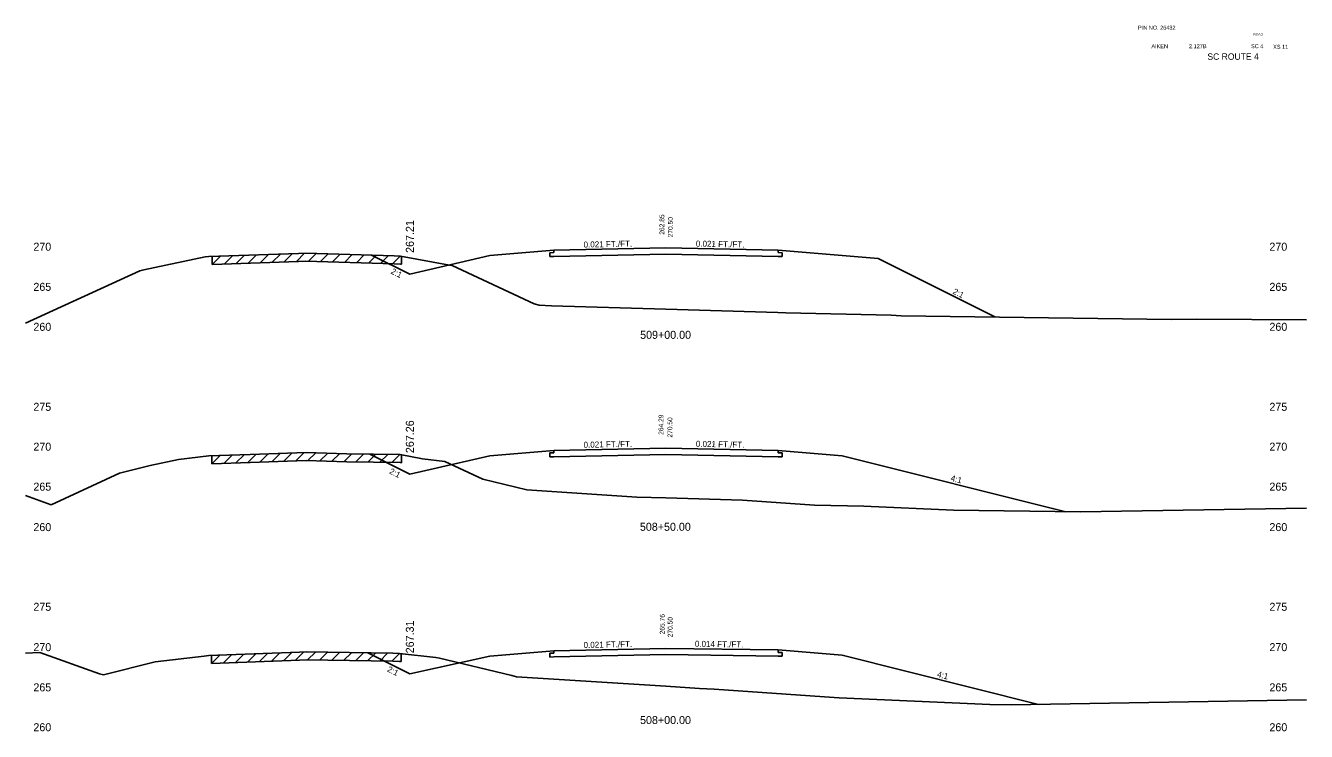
# Model space of a CAD drawing. Extents: x 883 to 1160, y 1002 to 4323.
# Drawn here: x 1000 to 1160, y 2165.1 to 2253.3 of the extents above; entities that cross this region are included whole.
import ezdxf

# ---------------------------------------------------------------- set-up
doc = ezdxf.new("R2010")
doc.units = 0
for name, color, linetype in [('Level 1', 7, 'Continuous'), ('Level 10', 7, 'Continuous'), ('Level 11', 7, 'Continuous'), ('Level 12', 7, 'Continuous'), ('Level 3', 7, 'Continuous'), ('Level 32', 7, 'Continuous'), ('Level 33', 7, 'Continuous'), ('Level 59', 7, 'Continuous'), ('Level 6', 7, 'Continuous'), ('Level 60', 7, 'Continuous'), ('Level 61', 7, 'Continuous'), ('Level 7', 7, 'Continuous')]:
    doc.layers.add(name, color=color, linetype=linetype)

msp = doc.modelspace()

# ---------------------------------------------------------------- linework, layer by layer
at = {"layer": 'Level 11'}
for p, q in [((1066, 2224.91), (1065.5, 2224.9)), ((1065.5, 2224.9), (1065.5, 2224.42)), ((1065.5, 2224.42), (1066, 2224.43)), ((1066, 2225.21), (1066, 2224.91)), ((1094, 2224.91), (1094, 2225.21)), ((1094.5, 2224.9), (1094, 2224.91)), ((1094, 2224.43), (1094.5, 2224.42)), ((1094.5, 2224.42), (1094.5, 2224.9)), ((1066, 2200.21), (1066, 2199.91)), ((1094, 2199.91), (1094, 2200.21)), ((1066, 2199.91), (1065.5, 2199.9)), ((1065.5, 2199.9), (1065.5, 2199.42)), ((1065.5, 2199.42), (1066, 2199.43)), ((1094.5, 2199.9), (1094, 2199.91)), ((1094, 2199.43), (1094.5, 2199.42)), ((1094.5, 2199.42), (1094.5, 2199.9)), ((1066, 2174.91), (1065.5, 2174.9)), ((1065.5, 2174.9), (1065.5, 2174.42)), ((1065.5, 2174.42), (1066, 2174.43)), ((1066, 2175.21), (1066, 2174.91)), ((1094, 2175), (1094, 2175.3)), ((1094.5, 2174.99), (1094, 2175)), ((1094, 2174.52), (1094.5, 2174.51)), ((1094.5, 2174.51), (1094.5, 2174.99))]:
    msp.add_line(p, q, dxfattribs=at)
at = {"layer": 'Level 12'}
for p, q in [((1080, 2224.72), (1066, 2224.43)), ((1094, 2224.43), (1080, 2224.72)), ((1080, 2199.72), (1066, 2199.43)), ((1094, 2199.43), (1080, 2199.72)), ((1080, 2174.72), (1066, 2174.43)), ((1094, 2174.52), (1080, 2174.72))]:
    msp.add_line(p, q, dxfattribs=at)
at = {"layer": 'Level 59'}
for p, q in [((1066, 2225.21), (1080, 2225.5)), ((1080, 2225.5), (1094, 2225.21)), ((1066, 2200.21), (1080, 2200.5)), ((1080, 2200.5), (1094, 2200.21)), ((1066, 2175.21), (1080, 2175.5)), ((1080, 2175.5), (1094, 2175.3))]:
    msp.add_line(p, q, dxfattribs=at)
at = {"layer": 'Level 6'}
for p, q in [((1058, 2224.54), (1066, 2225.21)), ((1094, 2225.21), (1106.5, 2224.17)), ((1058, 2199.54), (1066, 2200.21)), ((1094, 2200.21), (1102, 2199.54)), ((1058, 2174.54), (1066, 2175.21)), ((1094, 2175.3), (1102, 2174.63))]:
    msp.add_line(p, q, dxfattribs=at)
at = {"layer": 'Level 60'}
for p, q in [((1014.76, 2222.77), (1022.41, 2224.37)), ((1022.41, 2224.37), (1022.9, 2224.42)), ((1022.9, 2224.42), (1034.11, 2224.82)), ((1034.11, 2224.82), (1035, 2224.86)), ((1035, 2224.86), (1046.04, 2224.5)), ((1046.04, 2224.5), (1046.85, 2224.49)), ((1046.85, 2224.49), (1052.97, 2223.36)), ((1000, 2216.09), (1014.26, 2222.65)), ((1014.26, 2222.65), (1014.76, 2222.77)), ((1052.97, 2223.36), (1053.3, 2223.32)), ((1053.3, 2223.32), (1063.53, 2218.5)), ((1063.53, 2218.5), (1064.15, 2218.35)), ((1064.15, 2218.35), (1065.69, 2218.25)), ((1065.69, 2218.25), (1080, 2217.85)), ((1080, 2217.85), (1093.99, 2217.45)), ((1093.99, 2217.45), (1094.99, 2217.38)), ((1094.99, 2217.38), (1108.12, 2217.1)), ((1108.12, 2217.1), (1109.36, 2217.04)), ((1109.36, 2217.04), (1143.14, 2216.57)), ((1143.14, 2216.57), (1146.33, 2216.62)), ((1146.33, 2216.62), (1160, 2216.51)), ((1015.57, 2198.34), (1019.1, 2199.07)), ((1019.1, 2199.07), (1022.88, 2199.52)), ((1022.88, 2199.52), (1028.06, 2199.71)), ((1028.06, 2199.71), (1035.03, 2199.97)), ((1035.03, 2199.97), (1040.12, 2199.8)), ((1040.12, 2199.8), (1046.77, 2199.69)), ((1046.77, 2199.69), (1049.6, 2199.17)), ((1049.6, 2199.17), (1052.38, 2198.85)), ((1052.38, 2198.85), (1057.11, 2196.62)), ((1003.18, 2193.44), (1011.73, 2197.37)), ((1011.73, 2197.37), (1015.57, 2198.34)), ((1057.11, 2196.62), (1062.62, 2195.29)), ((1062.62, 2195.29), (1076.37, 2194.39)), ((1000, 2194.57), (1003.18, 2193.44)), ((1076.37, 2194.39), (1080, 2194.29)), ((1080, 2194.29), (1089.57, 2194.02)), ((1089.57, 2194.02), (1098.56, 2193.4)), ((1098.56, 2193.4), (1104.71, 2193.26)), ((1104.71, 2193.26), (1115.91, 2192.76)), ((1115.91, 2192.76), (1131.77, 2192.54)), ((1131.77, 2192.54), (1160, 2193.01)), ((1000, 2174.92), (1001.79, 2175)), ((1001.79, 2175), (1009.23, 2172.3)), ((1016.18, 2173.8), (1022.31, 2174.54)), ((1022.31, 2174.54), (1022.89, 2174.62)), ((1022.89, 2174.62), (1034.21, 2175.03)), ((1034.21, 2175.03), (1035.05, 2175.05)), ((1035.05, 2175.05), (1045.88, 2174.88)), ((1045.88, 2174.88), (1046.72, 2174.87)), ((1046.72, 2174.87), (1051.26, 2174.35)), ((1009.71, 2172.19), (1016.18, 2173.8)), ((1051.26, 2174.35), (1051.7, 2174.29)), ((1051.7, 2174.29), (1060.76, 2172.1)), ((1009.23, 2172.3), (1009.71, 2172.19)), ((1060.76, 2172.1), (1061.32, 2171.96)), ((1061.32, 2171.96), (1080, 2170.76)), ((1080, 2170.76), (1084.18, 2170.49)), ((1084.18, 2170.49), (1086.01, 2170.4)), ((1086.01, 2170.4), (1101.01, 2169.36)), ((1101.01, 2169.36), (1101.62, 2169.33)), ((1101.62, 2169.33), (1120.46, 2168.48)), ((1120.46, 2168.48), (1123.1, 2168.44)), ((1123.1, 2168.44), (1160, 2169.08))]:
    msp.add_line(p, q, dxfattribs=at)
at = {"layer": 'Level 61'}
for p, q in [((1024.35, 2224.48), (1023.32, 2223.44)), ((1023.32, 2224.44), (1023.32, 2223.44)), ((1025.85, 2224.53), (1024.82, 2223.49)), ((1027.35, 2224.58), (1026.32, 2223.55)), ((1028.85, 2224.64), (1027.82, 2223.6)), ((1030.35, 2224.69), (1029.32, 2223.65)), ((1031.85, 2224.74), (1030.82, 2223.71)), ((1033.35, 2224.8), (1032.32, 2223.76)), ((1034.85, 2224.85), (1033.82, 2223.81)), ((1036.28, 2224.82), (1035.32, 2223.85)), ((1037.78, 2224.77), (1036.82, 2223.8)), ((1039.28, 2224.72), (1038.32, 2223.75)), ((1040.78, 2224.67), (1039.82, 2223.7)), ((1042.28, 2224.62), (1041.32, 2223.65)), ((1043.78, 2224.57), (1042.82, 2223.61)), ((1045.28, 2224.53), (1044.32, 2223.56)), ((1046.8, 2224.49), (1045.82, 2223.51)), ((1046.97, 2223.47), (1046.97, 2224.47)), ((1023.32, 2223.44), (1034.11, 2223.82)), ((1034.11, 2223.82), (1035, 2223.86)), ((1035, 2223.86), (1046.04, 2223.5)), ((1046.04, 2223.5), (1046.85, 2223.49)), ((1046.85, 2223.49), (1046.97, 2223.47)), ((1024.31, 2199.58), (1023.27, 2198.54)), ((1023.27, 2199.54), (1023.27, 2198.54)), ((1023.27, 2198.54), (1028.06, 2198.71)), ((1025.81, 2199.63), (1024.77, 2198.59)), ((1027.31, 2199.68), (1026.27, 2198.65)), ((1028.81, 2199.74), (1027.77, 2198.7)), ((1028.06, 2198.71), (1035.03, 2198.97)), ((1030.31, 2199.79), (1029.27, 2198.75)), ((1031.81, 2199.85), (1030.77, 2198.81)), ((1033.31, 2199.9), (1032.27, 2198.86)), ((1034.81, 2199.96), (1033.77, 2198.92)), ((1035.03, 2198.97), (1040.12, 2198.8)), ((1036.24, 2199.93), (1035.27, 2198.96)), ((1037.74, 2199.88), (1036.77, 2198.91)), ((1039.24, 2199.83), (1038.27, 2198.86)), ((1040.75, 2199.79), (1039.77, 2198.81)), ((1040.12, 2198.8), (1046.77, 2198.69)), ((1042.26, 2199.77), (1041.27, 2198.78)), ((1043.76, 2199.74), (1042.77, 2198.76)), ((1045.26, 2199.72), (1044.27, 2198.73)), ((1046.76, 2199.69), (1045.77, 2198.71)), ((1046.77, 2198.69), (1046.95, 2198.66)), ((1046.95, 2198.66), (1046.95, 2199.66)), ((1024.27, 2174.67), (1023.23, 2173.63)), ((1023.23, 2174.63), (1023.23, 2173.63)), ((1025.77, 2174.72), (1024.73, 2173.68)), ((1027.27, 2174.78), (1026.23, 2173.74)), ((1028.77, 2174.83), (1027.73, 2173.79)), ((1030.27, 2174.89), (1029.23, 2173.85)), ((1031.77, 2174.94), (1030.73, 2173.9)), ((1033.27, 2175), (1032.23, 2173.96)), ((1034.76, 2175.05), (1033.73, 2174.02)), ((1036.22, 2175.03), (1035.23, 2174.05)), ((1037.72, 2175.01), (1036.73, 2174.02)), ((1039.22, 2174.98), (1038.23, 2174)), ((1040.72, 2174.96), (1039.73, 2173.98)), ((1042.22, 2174.94), (1041.23, 2173.95)), ((1043.72, 2174.91), (1042.73, 2173.93)), ((1045.22, 2174.89), (1044.23, 2173.9)), ((1046.72, 2174.87), (1045.73, 2173.88)), ((1046.93, 2173.85), (1046.93, 2174.85)), ((1023.23, 2173.63), (1034.21, 2174.03)), ((1034.21, 2174.03), (1035.05, 2174.05)), ((1035.05, 2174.05), (1045.88, 2173.88)), ((1045.88, 2173.88), (1046.72, 2173.87)), ((1046.72, 2173.87), (1046.93, 2173.85))]:
    msp.add_line(p, q, dxfattribs=at)
at = {"layer": 'Level 7'}
for p, q in [((1043.23, 2224.59), (1048, 2222.21)), ((1048, 2222.21), (1058, 2224.54)), ((1106.5, 2224.17), (1121.08, 2216.88)), ((1043, 2199.76), (1048, 2197.26)), ((1048, 2197.26), (1058, 2199.54)), ((1102, 2199.54), (1129.93, 2192.56)), ((1042.76, 2174.93), (1048, 2172.31)), ((1048, 2172.31), (1058, 2174.54)), ((1102, 2174.63), (1126.53, 2168.5))]:
    msp.add_line(p, q, dxfattribs=at)

# ---------------------------------------------------------------- texts
at = {"layer": 'Level 1'}
for s, height, p in [('PIN NO. 26432', 0.5, (1138.97, 2252.75)), ('AIKEN', 0.5, (1140.64, 2250.44)), (' 2.127B', 0.5, (1145.15, 2250.44)), ('SC ROUTE 4', 0.8, (1147.63, 2248.99)), ('SC 4', 0.5, (1153.09, 2250.44)), ('XS 11', 0.5, (1155.85, 2250.36)), ('509+00.00', 1, (1076.77, 2214.15)), ('508+50.00', 1, (1076.74, 2190.18)), ('508+00.00', 1, (1076.76, 2166.05))]:
    msp.add_text(s, height=height, dxfattribs=at).set_placement(p)
at = {"layer": 'Level 10'}
for s, p in [('262.85', (1079.79, 2227.15)), ('264.29', (1079.67, 2202.16)), ('265.76', (1079.83, 2177.25))]:
    msp.add_text(s, height=0.6, rotation=90, dxfattribs=at).set_placement(p)
at = {"layer": 'Level 3'}
for s, height, p in [('ROAD', 0.3, (1153.38, 2252.02)), (' 270', 1, (1000.6, 2225.15)), (' 270', 1, (1155.01, 2225.15)), (' 265', 1, (1000.6, 2220.14)), (' 265', 1, (1155.01, 2220.14)), (' 260', 1, (1000.6, 2215.15)), (' 260', 1, (1155.01, 2215.15)), (' 275', 1, (1000.6, 2205.16)), (' 275', 1, (1155.01, 2205.16)), (' 270', 1, (1000.6, 2200.18)), (' 270', 1, (1155.01, 2200.18)), (' 265', 1, (1000.6, 2195.19)), (' 265', 1, (1155.01, 2195.19)), (' 260', 1, (1000.6, 2190.14)), (' 260', 1, (1155.01, 2190.14)), (' 275', 1, (1000.6, 2180.19)), (' 275', 1, (1155.01, 2180.19)), (' 270', 1, (1000.6, 2175.15)), (' 270', 1, (1155.01, 2175.15)), (' 265', 1, (1000.6, 2170.13)), (' 265', 1, (1155.01, 2170.13)), (' 260', 1, (1000.6, 2165.15)), (' 260', 1, (1155.01, 2165.15))]:
    msp.add_text(s, height=height, dxfattribs=at).set_placement(p)
at = {"layer": 'Level 32'}
for s, rotation, p in [('0.021 FT./FT.', 1.1916, (1069.71, 2225.54)), ('0.021 FT./FT.', 358.8084, (1083.72, 2225.67)), ('2:1', 333.435, (1045.55, 2222.34)), ('2:1', 333.435, (1115.75, 2219.82)), ('0.021 FT./FT.', 1.1916, (1069.71, 2200.54)), ('0.021 FT./FT.', 358.8084, (1083.72, 2200.67)), ('2:1', 333.435, (1045.36, 2197.37)), ('4:1', 345.9638, (1115.51, 2196.42)), ('0.021 FT./FT.', 1.1916, (1069.71, 2175.54)), ('0.014 FT./FT.', 359.1793, (1083.6, 2175.7)), ('2:1', 333.435, (1045.1, 2172.65)), ('4:1', 345.9638, (1113.81, 2171.94))]:
    msp.add_text(s, height=0.75, rotation=rotation, dxfattribs=at).set_placement(p)
at = {"layer": 'Level 33'}
for s, p in [('267.21', (1048.5, 2224.88)), ('267.26', (1048.5, 2199.88)), ('267.31', (1048.5, 2174.88))]:
    msp.add_text(s, height=1, rotation=90, dxfattribs=at).set_placement(p)
at = {"layer": 'Level 59'}
for p in [(1080.85, 2226.59), (1080.79, 2201.59), (1080.82, 2176.65)]:
    msp.add_text(' 270.50', height=0.6, rotation=90, dxfattribs=at).set_placement(p)

doc.saveas('drawing.dxf')
